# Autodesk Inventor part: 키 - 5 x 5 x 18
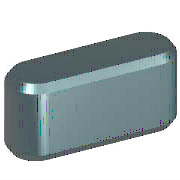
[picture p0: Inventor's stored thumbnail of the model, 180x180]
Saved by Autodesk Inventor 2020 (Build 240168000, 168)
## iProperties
Created: 2012-02
Part Number: 키 - 5 x 5 x 18
Material: 강철, 연강
Description: 키 및 해당 키홈
Document SubType Name: Modeling
Standard: KS B 1311
Designer: mduedu
Standards Organization: KS
Language: ko-KR
Size Designation: 5 x 5 x 18
Categories: <MemberInstance><Categories><Category DisplayName="샤프트 부품" InternalName="7f7aeb1f-a693-4053-b835-cee3144e0d98" Mnemonic="SHFT"><Category DisplayName="키" Interna
Density: 7.86 g/cm^3
Mass: 3.27476 g
Surface Area: 3.57848 cm^2
Volume: 0.416636 cm^3
Appearance: 노란색
IsCustomPart: 1
Author: mduedu
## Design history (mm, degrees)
workplane "Work Plane1"
workplane "Work Plane2"
sketch "스케치1"
  geometry: L1 (2.5, 2.5)-(15.5, 2.5); L2 (15.5, -2.5)-(2.5, -2.5); L3 (0, 9.4)-(0, -7.4) reference; L4 (-5, 0)-(30, 0) reference; L5 (18, 0)-(18, 7); A1 r 2.5 centre (2.5, 0) between (2.5, 2.5) and (2.5, -2.5); A2 r 2.5 centre (15.5, 0) between (15.5, -2.5) and (15.5, 2.5)
  constraints: 6 end point, 5 point on circle, 4 tangent, 3 point on line, 2 centre point, 1 horizontal, 1 parallel, 1 perpendicular
  dimensions: "d0" = 2.5 radius of A1 (= 0.5 x PB); "d13" = 2.5 radius of A2 (= 0.5 x PB); "d14" = 18 distance between parallel lines of L5 L3 (= NLG)
extrude "본체1" new body sketch "스케치1" taper "d3" = 0 deg; stored distance "d4" = 10
workplane "Work Plane3"
body "Solid1"
chamfer "모따기1" distance "d8" = 0.4 (= PHH); stored, may be unused: second distance "d9" = 0.4 (= PHH), angle "d15" = 45 deg
other parameters: "d1" = -3 (= -PNT), "d2" = 2 (= PH - PNT), "NLG" = 18 [user parameter; used in 3 equation terms], "PB" = 5 [user parameter; used in 2 equation terms], "PNT" = 3 [user parameter; used in 2 equation terms], "PH" = 5 [user parameter; used in 1 equation term], "PHH" = 0.4 [user parameter; used in 2 equation terms], "d10" = 0, "d16" = 0, "d17" = 0, "d18" = 0, "WDMIN" = 12 [user parameter], "PLB2" = 18 (= NLG) [user parameter], "WDMAX" = 17 [user parameter], "PLB1" = 18 (= NLG) [user parameter], "RR" = 0.16 [user parameter], "PUEB" = 2.3 [user parameter]
